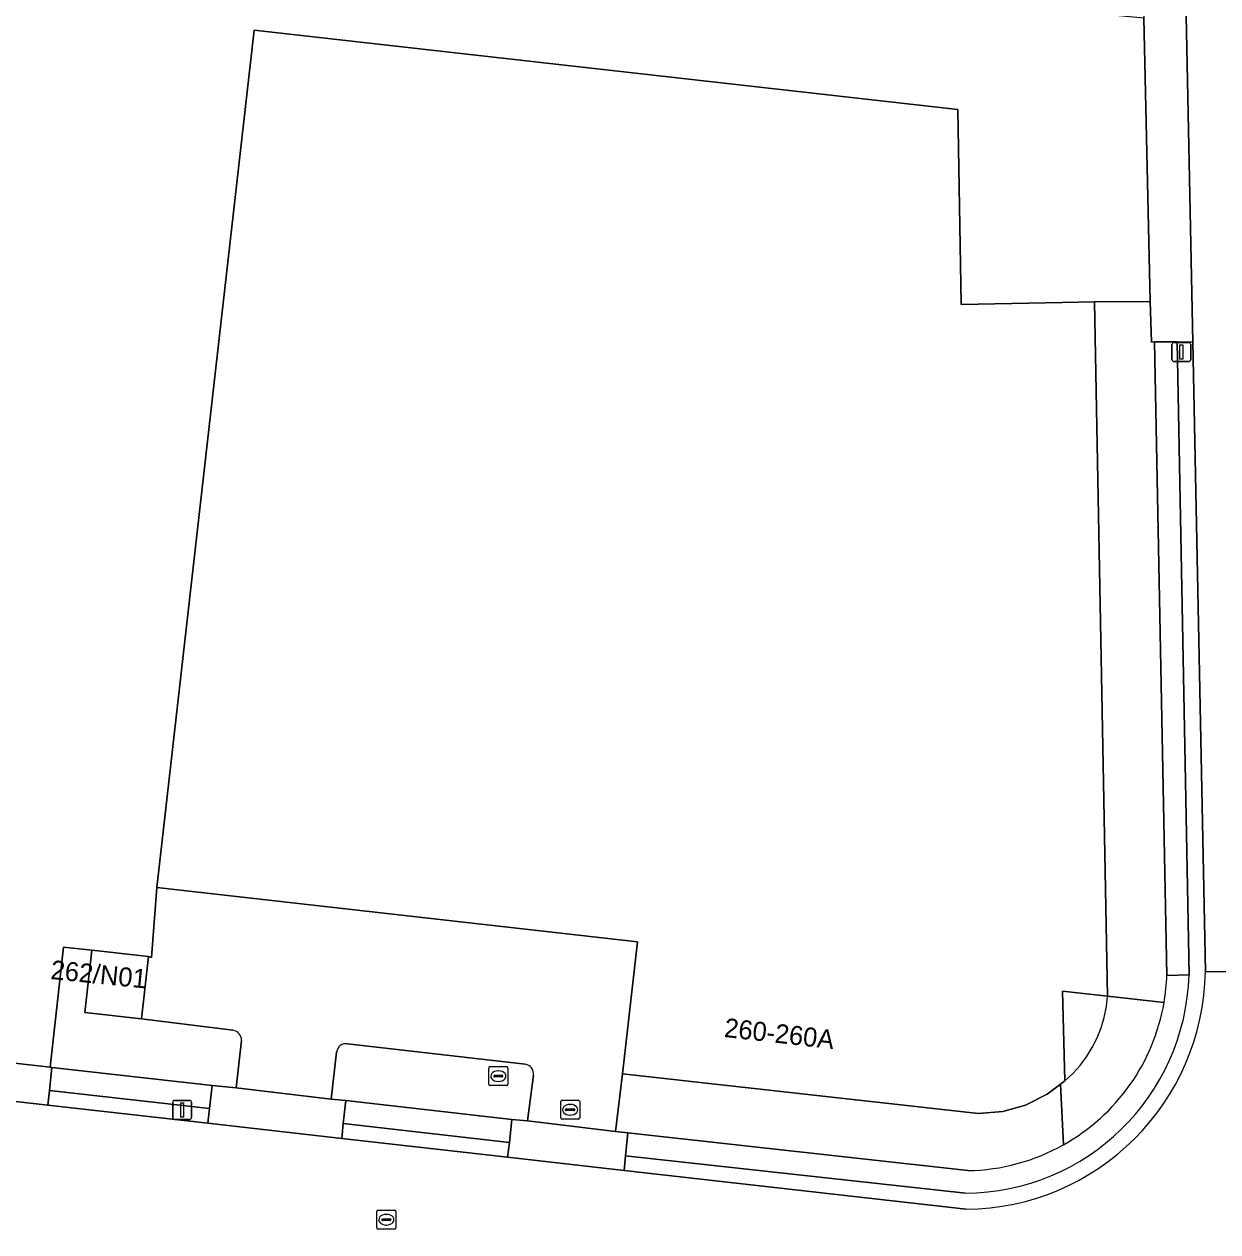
# Model space of a CAD drawing. Extents: x 161385 to 162589, y 388479 to 389756.
# Drawn here: x 162433.2 to 162496, y 388787.2 to 388850.8 of the extents above; entities that cross this region are included whole.
import ezdxf

# ---------------------------------------------------------------- set-up
doc = ezdxf.new("R2010")
doc.units = 0
for name, color, linetype in [('IMGEO_Berm_groen', 7, 'Continuous'), ('IMGEO_Erf', 7, 'Continuous'), ('IMGEO_Groenvoorziening', 7, 'Continuous'), ('IMGEO_Kolk', 7, 'Continuous'), ('IMGEO_Lichtmast', 7, 'Continuous'), ('IMGEO_Pand', 7, 'Continuous'), ('IMGEO_Pand_nummerreeks', 7, 'Continuous'), ('IMGEO_Pand_overbouw', 7, 'Continuous'), ('IMGEO_Parkeervlak_open', 7, 'Continuous'), ('IMGEO_Rijbaan_lokaal_gesloten', 7, 'Continuous'), ('IMGEO_Rioolput', 7, 'Continuous'), ('IMGEO_Voetpad_open', 7, 'Continuous')]:
    doc.layers.add(name, color=color, linetype=linetype)

msp = doc.modelspace()

# ---------------------------------------------------------------- linework, layer by layer
at = {"layer": 'IMGEO_Berm_groen'}
for points in [[(162494.665, 388834.017), (162493.855, 388834.039), (162494.47, 388800.72)], [(162495.332, 388800.906), (162494.665, 388834.017)], [(162482.704, 388789.231), (162464.825, 388791.196), (162464.75, 388790.426), (162482.74, 388788.383)]]:
    msp.add_lwpolyline(points, dxfattribs=at)
for points in [[(162434.513, 388794.642), (162434.425, 388793.87), (162442.854, 388792.912), (162442.943, 388793.684)], [(162449.978, 388792.905), (162449.905, 388792.112), (162458.615, 388791.123), (162458.713, 388791.9)]]:
    msp.add_lwpolyline(points, close=True, dxfattribs=at)
for centre, radius, start, end in [((162482.638, 388801.068), 11.837, 270.32027, 358.31484), ((162482.624, 388801.092), 12.709, 270.52177, 359.1634)]:
    msp.add_arc(centre, radius, start, end, dxfattribs=at)
at = {"layer": 'IMGEO_Erf'}
msp.add_lwpolyline([(162423.214, 388797.141), (162434.552, 388795.859), (162435.263, 388802.18), (162436.753, 388802.017), (162439.735, 388801.682), (162439.879, 388801.637), (162440.168, 388805.317), (162445.286, 388850.441), (162482.306, 388846.26), (162482.466, 388837.077), (162482.487, 388836.004), (162487.823, 388836.098), (162489.492, 388836.131), (162492.433, 388836.158), (162492.098, 388851.061), (162487.953, 388851.459), (162488.523, 388856.678), (162488.541, 388856.845), (162437.609, 388862.581), (162440.94, 388892.207), (162488.443, 388886.892), (162488.497, 388887.644), (162491.565, 388887.495), (162491.458, 388892.887)], dxfattribs=at)
at = {"layer": 'IMGEO_Groenvoorziening'}
for points in [[(162493.303, 388800.69), (162492.653, 388834.028), (162492.489, 388834.022), (162492.433, 388836.158), (162489.492, 388836.131), (162490.185, 388799.601), (162493.157, 388799.274)], [(162439.367, 388798.403), (162436.385, 388798.738), (162436.753, 388802.017), (162435.263, 388802.18), (162434.552, 388795.859), (162434.65, 388795.848), (162443.078, 388794.899), (162444.338, 388794.771), (162444.626, 388797.272)], [(162444.17, 388797.808), (162439.367, 388798.403)], [(162449.624, 388796.661), (162449.338, 388794.177), (162450.111, 388794.107), (162458.846, 388793.115), (162459.672, 388793.036), (162459.984, 388795.44)], [(162459.544, 388796.016), (162450.197, 388797.095)], [(162487.864, 388791.777), (162487.709, 388794.973), (162487.001, 388794.438), (162485.875, 388793.872), (162484.671, 388793.525), (162483.397, 388793.418), (162464.664, 388795.518), (162464.296, 388792.481), (162464.945, 388792.409), (162482.842, 388790.419)]]:
    msp.add_lwpolyline(points, dxfattribs=at)
for centre, radius, start, end in [((162482.778, 388801.06), 10.532, 350.23804, 357.98833), ((162444.089, 388797.277), 0.537, 359.47863, 81.30007), ((162450.123, 388796.597), 0.503, 81.58842, 172.6934), ((162459.485, 388795.515), 0.505, 351.49134, 83.26028), ((162482.654, 388801.08), 10.663, 271.01175, 299.2512)]:
    msp.add_arc(centre, radius, start, end, dxfattribs=at)
at = {"layer": 'IMGEO_Kolk'}
for p, q in [((162461.489, 388794.123), (162462.341, 388794.123)), ((162461.414, 388793.197), (162461.414, 388794.049)), ((162461.673, 388793.617), (162461.673, 388793.629)), ((162462.111, 388793.58), (162461.713, 388793.58)), ((162461.716, 388793.666), (162462.114, 388793.666)), ((162461.902, 388793.903), (162461.927, 388793.903)), ((162462.157, 388793.629), (162462.157, 388793.617)), ((162462.415, 388794.049), (162462.415, 388793.197)), ((162462.341, 388793.123), (162461.489, 388793.123)), ((162461.925, 388793.343), (162461.9, 388793.343))]:
    msp.add_line(p, q, dxfattribs=at)
for points in [[(162461.489, 388794.123), (162462.341, 388794.123)], [(162461.414, 388793.197), (162461.414, 388794.049)], [(162462.415, 388794.049), (162462.415, 388793.197)], [(162462.341, 388793.123), (162461.489, 388793.123)]]:
    msp.add_lwpolyline(points, dxfattribs=at)
for centre, radius, start, end in [((162461.491, 388794.047), 0.0765, 91.55205, 178.44795), ((162461.491, 388794.047), 0.0765, 91.55205, 178.44795), ((162462.339, 388794.047), 0.0765, 1.55205, 88.44795), ((162462.339, 388794.047), 0.0765, 1.55205, 88.44795), ((162461.713, 388793.626), 0.0403, 85.87752, 175.75265), ((162461.71, 388793.616), 0.0366, 178.93798, 274.71019), ((162462.114, 388793.623), 0.043, 264.86636, 352.45326), ((162462.118, 388793.628), 0.0386, 1.73085, 96.63898), ((162461.491, 388793.199), 0.0765, 181.55205, 268.44795), ((162461.491, 388793.199), 0.0765, 181.55205, 268.44795), ((162462.339, 388793.199), 0.0765, 271.55205, 358.44795), ((162462.339, 388793.199), 0.0765, 271.55205, 358.44795)]:
    msp.add_arc(centre, radius, start, end, dxfattribs=at)
for centre, major_axis, ratio, start_param, end_param in [((162461.901, 388793.623), (-0.387, 0.002), 0.722429, 4.712389, 7.853982), ((162461.926, 388793.623), (-0.39, 0.002), 0.717154, 1.570796, 4.712389)]:
    msp.add_ellipse(centre, major_axis=major_axis, ratio=ratio, start_param=start_param, end_param=end_param, dxfattribs=at)
at = {"layer": 'IMGEO_Lichtmast'}
for p, q in [((162493.575, 388833.098), (162493.575, 388833.898)), ((162493.575, 388833.898), (162493.575, 388833.098)), ((162493.675, 388833.998), (162494.465, 388833.998)), ((162494.465, 388833.998), (162493.675, 388833.998)), ((162494.565, 388833.898), (162494.565, 388833.098)), ((162494.565, 388833.098), (162494.565, 388833.898)), ((162494.465, 388832.998), (162493.675, 388832.998)), ((162493.675, 388832.998), (162494.465, 388832.998)), ((162441.103, 388794.116), (162441.893, 388794.116)), ((162441.893, 388794.116), (162441.103, 388794.116)), ((162441.003, 388793.216), (162441.003, 388794.016)), ((162441.003, 388794.016), (162441.003, 388793.216)), ((162441.993, 388794.016), (162441.993, 388793.216)), ((162441.993, 388793.216), (162441.993, 388794.016)), ((162441.893, 388793.116), (162441.103, 388793.116)), ((162441.103, 388793.116), (162441.893, 388793.116))]:
    msp.add_line(p, q, dxfattribs=at)
for points in [[(162493.995, 388833.873), (162494.145, 388833.873), (162494.145, 388833.123), (162493.995, 388833.123), (162493.995, 388833.873)], [(162441.423, 388793.991), (162441.573, 388793.991), (162441.573, 388793.241), (162441.423, 388793.241), (162441.423, 388793.991)]]:
    msp.add_lwpolyline(points, dxfattribs=at)
for centre, start, end in [((162493.675, 388833.898), 90, 180), ((162493.675, 388833.898), 90, 180), ((162494.465, 388833.898), 0, 90), ((162494.465, 388833.898), 360, 90), ((162493.675, 388833.098), 180, 270), ((162493.675, 388833.098), 180, 270), ((162494.465, 388833.098), 270, 0), ((162494.465, 388833.098), 270, 0), ((162441.103, 388794.016), 90, 180), ((162441.103, 388794.016), 90, 180), ((162441.893, 388794.016), 0, 90), ((162441.893, 388794.016), 360, 90), ((162441.103, 388793.216), 180, 270), ((162441.103, 388793.216), 180, 270), ((162441.893, 388793.216), 270, 0), ((162441.893, 388793.216), 270, 0)]:
    msp.add_arc(centre, 0.1, start, end, dxfattribs=at)
at = {"layer": 'IMGEO_Pand'}
for points in [[(162483.397, 388793.418), (162484.671, 388793.525), (162485.875, 388793.872), (162487.001, 388794.438), (162487.709, 388794.973), (162487.941, 388795.148), (162487.82, 388799.861), (162490.185, 388799.601), (162489.492, 388836.131), (162487.823, 388836.098), (162482.487, 388836.004), (162482.466, 388837.077), (162482.306, 388846.26), (162445.286, 388850.441), (162440.168, 388805.317), (162465.452, 388802.451), (162464.664, 388795.518)], [(162439.367, 388798.403), (162439.735, 388801.682), (162436.753, 388802.017), (162436.385, 388798.738)]]:
    msp.add_lwpolyline(points, close=True, dxfattribs=at)
at = {"layer": 'IMGEO_Pand_overbouw'}
msp.add_lwpolyline([(162490.185, 388799.601), (162487.82, 388799.861), (162487.941, 388795.148), (162488.358, 388795.535), (162488.739, 388795.958), (162489.08, 388796.413), (162489.379, 388796.898), (162489.64, 388797.411), (162489.846, 388797.933), (162490.009, 388798.478), (162490.126, 388799.05)], close=True, dxfattribs=at)
at = {"layer": 'IMGEO_Parkeervlak_open'}
for points in [[(162459.984, 388795.44), (162459.672, 388793.036), (162464.296, 388792.481), (162464.664, 388795.518), (162465.452, 388802.451), (162440.168, 388805.317), (162439.879, 388801.637), (162439.735, 388801.682), (162439.367, 388798.403), (162444.17, 388797.808)], [(162444.626, 388797.272), (162444.338, 388794.771), (162449.338, 388794.177), (162449.624, 388796.661)], [(162450.197, 388797.095), (162459.544, 388796.016)]]:
    msp.add_lwpolyline(points, dxfattribs=at)
for centre, radius, start, end in [((162444.089, 388797.277), 0.537, 359.47863, 81.30007), ((162450.123, 388796.597), 0.503, 81.58842, 172.6934), ((162459.485, 388795.515), 0.505, 351.49134, 83.26028)]:
    msp.add_arc(centre, radius, start, end, dxfattribs=at)
at = {"layer": 'IMGEO_Rijbaan_lokaal_gesloten'}
for points in [[(162493.479, 388892.905), (162493.608, 388886.494), (162494.075, 388863.303), (162494.213, 388856.462), (162494.284, 388852.938), (162494.665, 388834.017), (162495.332, 388800.906), (162502.522, 388800.855), (162502.515, 388801.899), (162502.076, 388822.868), (162501.627, 388843.777), (162500.817, 388885.662), (162500.546, 388899.883)], [(162496.642, 388786.698), (162497.837, 388787.967), (162498.913, 388789.338), (162499.863, 388790.8), (162500, 388791.038), (162500.793, 388792.59), (162501.444, 388794.206), (162501.949, 388795.874), (162502.302, 388797.58), (162502.501, 388799.311), (162502.53, 388799.811), (162502.522, 388800.855), (162495.332, 388800.906)], [(162434.425, 388793.87), (162423.146, 388795.15)], [(162482.74, 388788.383), (162464.75, 388790.426), (162458.615, 388791.123), (162449.905, 388792.112), (162442.854, 388792.912), (162434.425, 388793.87)]]:
    msp.add_lwpolyline(points, dxfattribs=at)
msp.add_arc((162482.624, 388801.092), 12.709, 270.52177, 359.1634, dxfattribs=at)
at = {"layer": 'IMGEO_Rioolput'}
for p, q in [((162457.635, 388794.966), (162457.635, 388795.818)), ((162457.71, 388795.892), (162458.562, 388795.892)), ((162457.894, 388795.386), (162457.894, 388795.398)), ((162457.937, 388795.435), (162458.335, 388795.435)), ((162458.123, 388795.672), (162458.148, 388795.672)), ((162458.378, 388795.398), (162458.378, 388795.386)), ((162458.636, 388795.818), (162458.636, 388794.966)), ((162458.562, 388794.892), (162457.71, 388794.892)), ((162458.332, 388795.349), (162457.934, 388795.349)), ((162458.146, 388795.112), (162458.121, 388795.112)), ((162451.743, 388787.412), (162451.743, 388788.264)), ((162451.818, 388788.338), (162452.67, 388788.338)), ((162452.002, 388787.832), (162452.002, 388787.844)), ((162452.44, 388787.795), (162452.042, 388787.795)), ((162452.045, 388787.881), (162452.443, 388787.881)), ((162452.231, 388788.118), (162452.256, 388788.118)), ((162452.486, 388787.844), (162452.486, 388787.832)), ((162452.744, 388788.264), (162452.744, 388787.412)), ((162452.67, 388787.338), (162451.818, 388787.338)), ((162452.254, 388787.558), (162452.229, 388787.558))]:
    msp.add_line(p, q, dxfattribs=at)
for points in [[(162457.635, 388794.966), (162457.635, 388795.818)], [(162457.71, 388795.892), (162458.562, 388795.892)], [(162458.636, 388795.818), (162458.636, 388794.966)], [(162458.562, 388794.892), (162457.71, 388794.892)], [(162451.743, 388787.412), (162451.743, 388788.264)], [(162451.818, 388788.338), (162452.67, 388788.338)], [(162452.744, 388788.264), (162452.744, 388787.412)], [(162452.67, 388787.338), (162451.818, 388787.338)]]:
    msp.add_lwpolyline(points, dxfattribs=at)
for centre, radius, start, end in [((162457.712, 388795.816), 0.0765, 91.55205, 178.44795), ((162457.712, 388795.816), 0.0765, 91.55205, 178.44795), ((162457.934, 388795.395), 0.0403, 85.87752, 175.75265), ((162457.931, 388795.385), 0.0366, 178.93798, 274.71019), ((162458.335, 388795.392), 0.043, 264.86636, 352.45326), ((162458.339, 388795.397), 0.0386, 1.73085, 96.63898), ((162458.56, 388795.816), 0.0765, 1.55205, 88.44795), ((162458.56, 388795.816), 0.0765, 1.55205, 88.44795), ((162457.712, 388794.968), 0.0765, 181.55205, 268.44795), ((162457.712, 388794.968), 0.0765, 181.55205, 268.44795), ((162458.56, 388794.968), 0.0765, 271.55205, 358.44795), ((162458.56, 388794.968), 0.0765, 271.55205, 358.44795), ((162451.82, 388788.262), 0.0765, 91.55205, 178.44795), ((162451.82, 388788.262), 0.0765, 91.55205, 178.44795), ((162452.042, 388787.841), 0.0403, 85.87752, 175.75265), ((162452.039, 388787.831), 0.0366, 178.93798, 274.71019), ((162452.443, 388787.838), 0.043, 264.86636, 352.45326), ((162452.447, 388787.843), 0.0386, 1.73085, 96.63898), ((162452.668, 388788.262), 0.0765, 1.55205, 88.44795), ((162452.668, 388788.262), 0.0765, 1.55205, 88.44795), ((162451.82, 388787.414), 0.0765, 181.55205, 268.44795), ((162451.82, 388787.414), 0.0765, 181.55205, 268.44795), ((162452.668, 388787.414), 0.0765, 271.55205, 358.44795), ((162452.668, 388787.414), 0.0765, 271.55205, 358.44795)]:
    msp.add_arc(centre, radius, start, end, dxfattribs=at)
for centre, major_axis, ratio, start_param, end_param in [((162458.122, 388795.392), (-0.387, 0.002), 0.722429, 4.712389, 7.853982), ((162458.147, 388795.392), (-0.39, 0.002), 0.717154, 1.570796, 4.712389), ((162452.23, 388787.838), (-0.387, 0.002), 0.722429, 4.712389, 7.853982), ((162452.255, 388787.838), (-0.39, 0.002), 0.717154, 1.570796, 4.712389)]:
    msp.add_ellipse(centre, major_axis=major_axis, ratio=ratio, start_param=start_param, end_param=end_param, dxfattribs=at)
at = {"layer": 'IMGEO_Voetpad_open'}
for points in [[(162493.488, 388852.907), (162492.25, 388852.862), (162492.071, 388852.85), (162492.098, 388851.061), (162492.433, 388836.158), (162492.489, 388834.022), (162492.653, 388834.028), (162493.855, 388834.039), (162494.665, 388834.017), (162494.284, 388852.938)], [(162494.47, 388800.72), (162493.855, 388834.039), (162492.653, 388834.028), (162493.303, 388800.69)], [(162434.65, 388795.848), (162434.552, 388795.859), (162423.214, 388797.141), (162423.063, 388795.942), (162423.198, 388795.915), (162423.146, 388795.15), (162434.425, 388793.87), (162434.513, 388794.642)], [(162434.65, 388795.848), (162434.513, 388794.642), (162442.943, 388793.684), (162443.078, 388794.899)], [(162449.905, 388792.112), (162449.978, 388792.905), (162450.111, 388794.107), (162449.338, 388794.177), (162444.338, 388794.771), (162443.078, 388794.899), (162442.943, 388793.684), (162442.854, 388792.912)], [(162449.978, 388792.905), (162458.713, 388791.9), (162458.846, 388793.115), (162450.111, 388794.107)], [(162464.75, 388790.426), (162464.825, 388791.196), (162464.945, 388792.409), (162464.296, 388792.481), (162459.672, 388793.036), (162458.846, 388793.115), (162458.713, 388791.9), (162458.615, 388791.123)]]:
    msp.add_lwpolyline(points, close=True, dxfattribs=at)
for points in [[(162494.47, 388800.72), (162493.303, 388800.69)], [(162493.157, 388799.274), (162490.185, 388799.601), (162487.82, 388799.861), (162487.941, 388795.148), (162487.709, 388794.973), (162487.864, 388791.777)], [(162482.842, 388790.419), (162464.945, 388792.409), (162464.825, 388791.196), (162482.704, 388789.231)]]:
    msp.add_lwpolyline(points, dxfattribs=at)
for centre, radius, start, end in [((162482.638, 388801.068), 11.837, 270.32027, 358.31484), ((162482.778, 388801.06), 10.532, 350.23804, 357.98833), ((162482.657, 388801.07), 10.653, 299.26245, 350.29217), ((162482.657, 388801.07), 10.653, 299.26245, 350.29217), ((162482.654, 388801.08), 10.663, 271.01175, 299.2512)]:
    msp.add_arc(centre, radius, start, end, dxfattribs=at)

# ---------------------------------------------------------------- texts
at = {"layer": 'IMGEO_Pand_nummerreeks'}
for s, rotation, p in [('262/N01', 354.31629, (162434.549, 388800.505)), ('260-260A', 353.60375, (162469.983, 388797.458))]:
    msp.add_text(s, height=1, rotation=rotation, dxfattribs=at).set_placement(p)

doc.saveas('drawing.dxf')
